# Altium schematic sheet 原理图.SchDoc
size A3
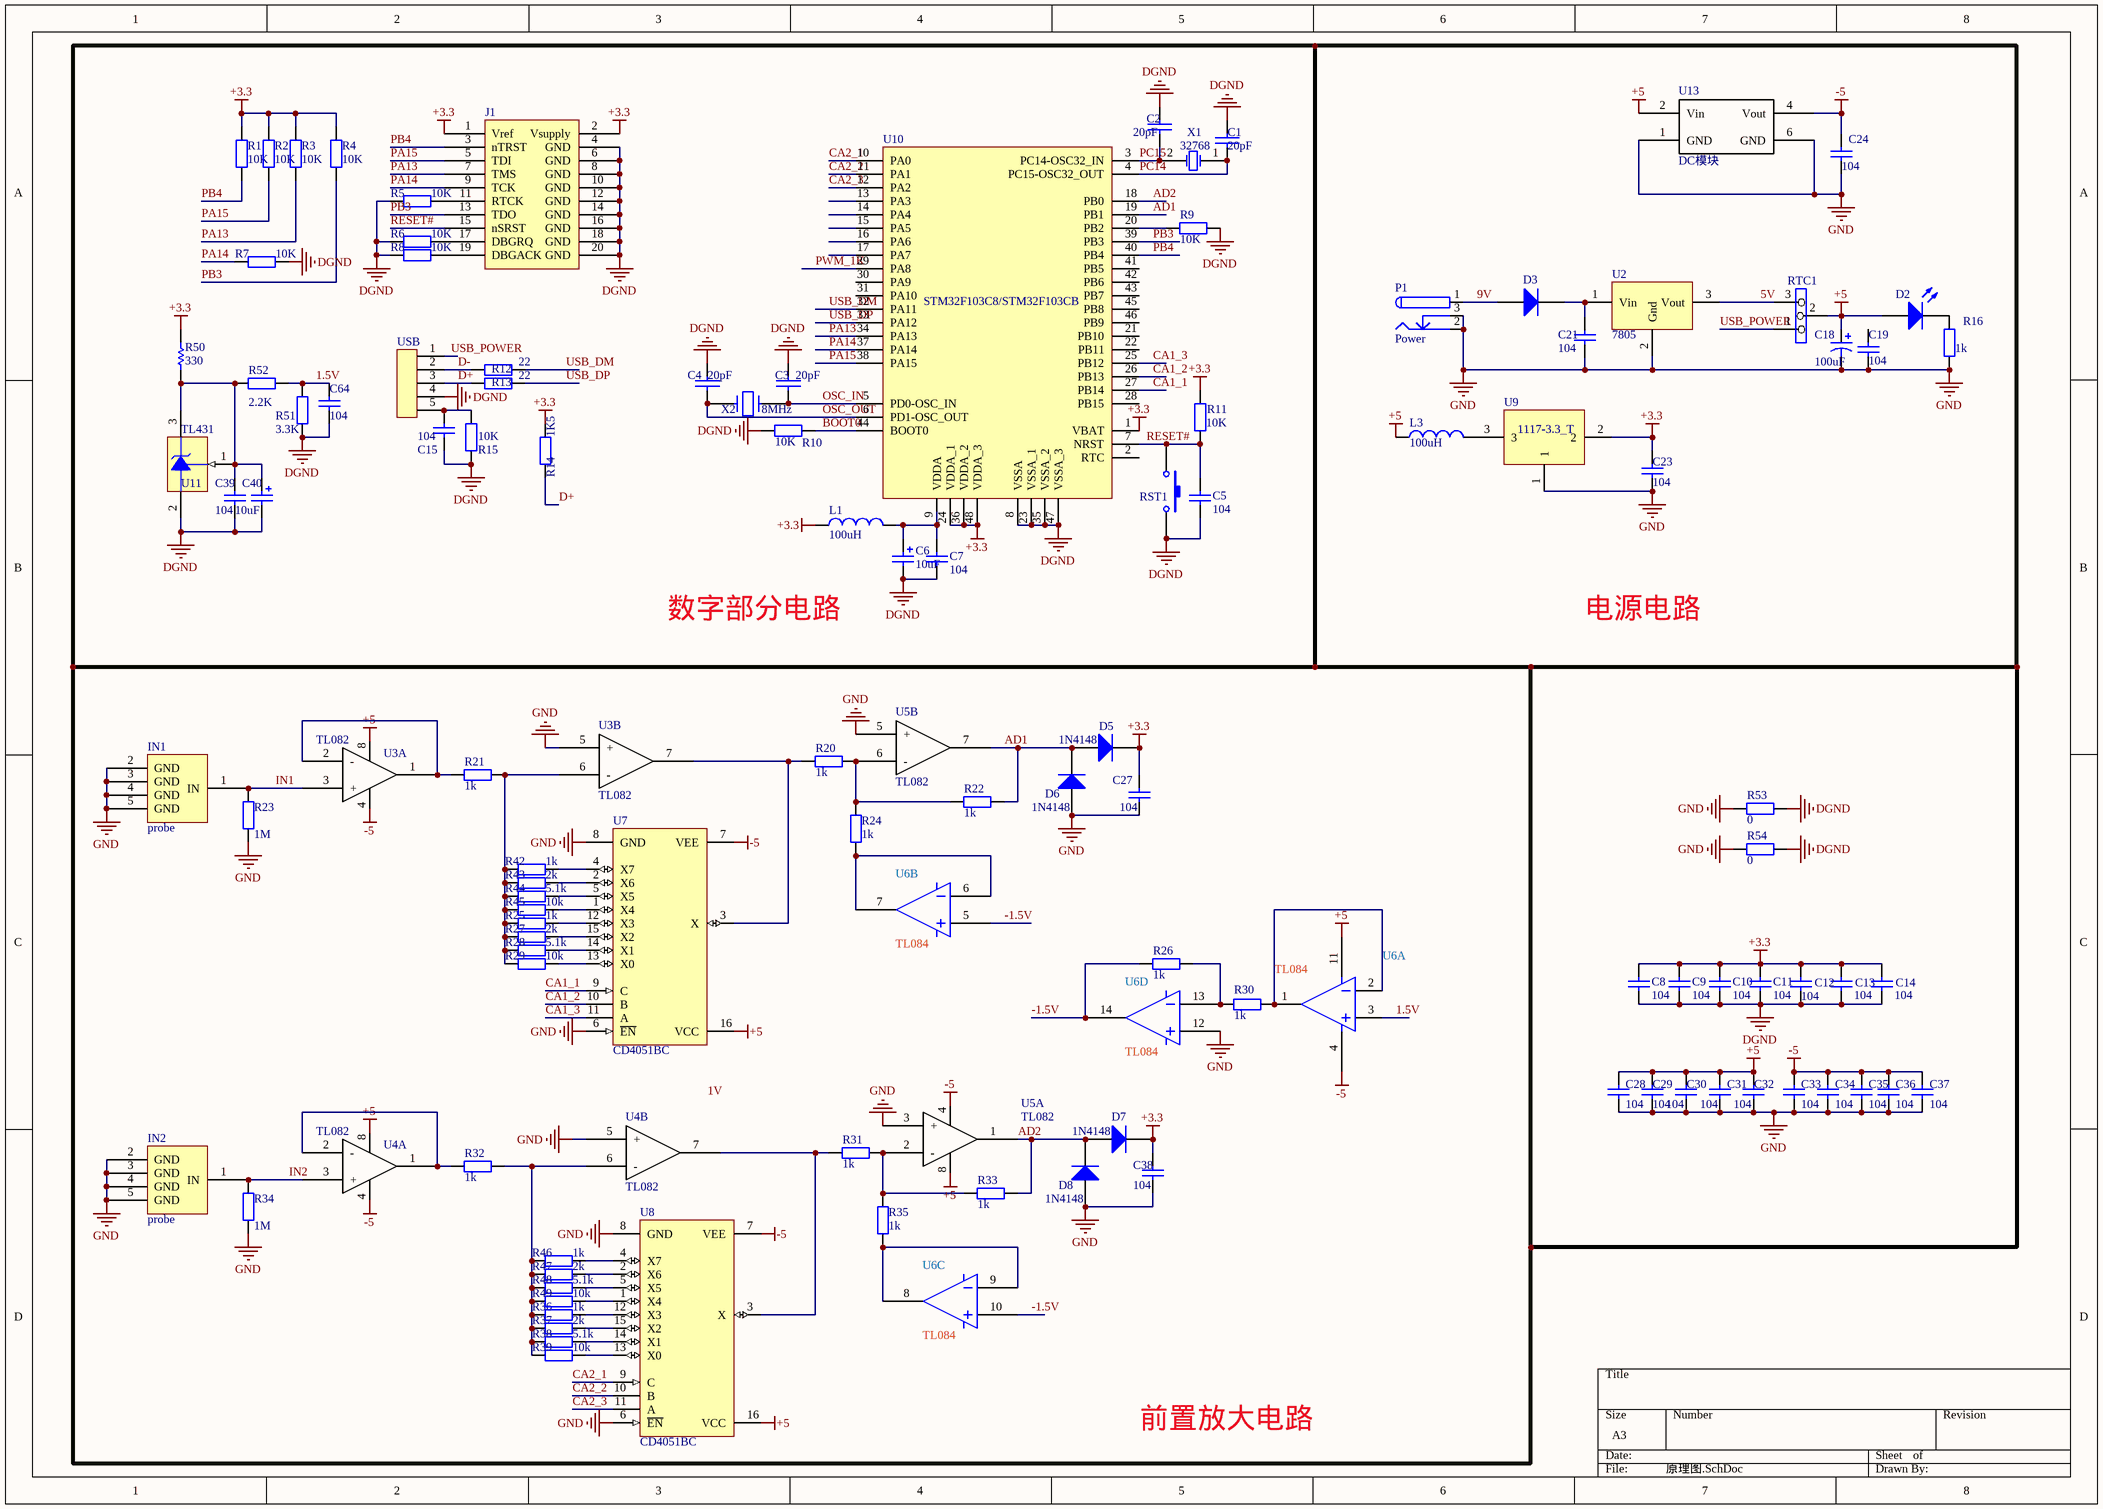
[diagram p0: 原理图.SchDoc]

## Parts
C1  20pF  [C0805]
C2  20pF  [C0805]
C3  20pF  [C0805]
C4  20pF  [C0805]
C5  104  [C0805]
C6  10uF  [C1206]
C7  104  [C0805]
C8  104  [C0805]
C9  104  [C0805]
C10  104  [C0805]
C11  value 104  [C0805]
C12  value 104  [C0805]
C13  104  [C0805]
C14  104  [C0805]
C15  104  [C0805]
C18  value 100uF  [C-100mil]  (hidden comment: 100u)
C19  104  [C0805]
C21  104  [C0805]
C23  104  [C0805]
C24  value 104  [0805]
C27  value 104  [C0805]
C28  104  [C0805]
C29  value 104  [C0805]
C30  value 104  [C0805]
C31  104  [C0805]
C32  value 104  [C0805]
C33  value 104  [C0805]
C34  104  [C0805]
C35  value 104  [C0805]
C36  104  [C0805]
C37  104  [C0805]
C38  value 104  [C0805]
C39  104  [C0805]
C40  10uF  [C1206]
C64  104  [C0805]
D2  LED  [c0805]  (value not drawn)
D3  1N4007  [DO-41]  (value not drawn)
D5  1N4148  [0805D]
D6  1N4148  [0805D]
D7  1N4148  [0805D]
D8  1N4148  [0805D]
IN1  probe  [̽ͷ]
IN2  probe  [̽ͷ]
J1  JTAG connector  [JTAG_20_T]  (value not drawn)
L1  value 100uH  [C0805]
L3  value 100uH  [c0805]
P1  Power  [Power_In]
R1  value 10K  [c0805]  (hidden comment: Res2)
R2  value 10K  [C0805]  (hidden comment: Res2)
R3  value 10K  [C0805]  (hidden comment: Res2)
R4  value 10K  [C0805]  (hidden comment: Res2)
R5  value 10K  [C0805]  (hidden comment: Res2)
R6  value 10K  [C0805]  (hidden comment: Res2)
R7  value 10K  [C0805]  (hidden comment: Res2)
R8  value 10K  [C0805]  (hidden comment: Res2)
R9  value 10K  [C0805]  (hidden comment: Res2)
R10  value 10K  [C0805]  (hidden comment: Res2)
R11  value 10K  [C0805]  (hidden comment: Res2)
R12  value 22  [C0805]
R13  22  [C0805]
R14  1K5  [C0805]
R15  10K  [C0805]
R16  1k  [C0805]
R20  1k  [C0805]
R21  1k  [C0805]
R22  1k  [C0805]
R23  value 1M  [C0805]  (hidden comment: Res2)
R24  1k  [C0805]
R25  1k  [C0805]
R26  1k  [C0805]
R27  value 2k  [C0805]  (hidden comment: 1k)
R28  value 5.1k  [C0805]  (hidden comment: 1k)
R29  value 10k  [C0805]  (hidden comment: 1k)
R30  1k  [C0805]
R31  1k  [C0805]
R32  1k  [C0805]
R33  1k  [C0805]
R34  value 1M  [C0805]  (hidden comment: Res2)
R35  1k  [C0805]
R36  1k  [C0805]
R37  value 2k  [C0805]  (hidden comment: 1k)
R38  value 5.1k  [C0805]  (hidden comment: 1k)
R39  value 10k  [C0805]  (hidden comment: 1k)
R42  1k  [C0805]
R43  value 2k  [C0805]  (hidden comment: 1k)
R44  value 5.1k  [C0805]  (hidden comment: 1k)
R45  value 10k  [C0805]  (hidden comment: 1k)
R46  1k  [C0805]
R47  value 2k  [C0805]  (hidden comment: 1k)
R48  value 5.1k  [C0805]  (hidden comment: 1k)
R49  value 10k  [C0805]  (hidden comment: 1k)
R50  330  [C0805]
R51  value 3.3K  [C0805]
R52  2.2K  [C0805]
R53  value 0  [C0805]  (hidden comment: 1k)
R54  value 0  [C0805]  (hidden comment: 1k)
RST1  SW-PB  [按键]  (value not drawn)
RTC1  (no value)  [PZ3]
U2  7805  [7805]
U3  TL082  [NE5532]  (parts A,B of 2)
U4  TL082  [NE5532]  (parts A,B of 2)
U5  TL082  [NE5532]  (parts A,B of 2)
U6  TL084  [SOIC14_1.27mm]  (parts A,B,C,D of 4)
U7  CD4051BC  [CD4051]
U8  CD4051BC  [CD4051]
U9  (no value)  [SOT223]
U10  STM32F103C8/STM32F103CB  [LQFP48]
U11  TL431  [sot-23]
U13  DC模块  [DC模块]
USB  (no value)  [USB-B]
X1  32768  [XTAL-32768]
X2  8MHz  [XTAL-200mil]

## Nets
+3.3: C8.2 C9.2 C10.2 C11.1 C12.1 C13.2 C14.2 C23.2 C27.1 C38.1 D5.2(K) D7.2(K) J1.1(Vref) J1.2(Vsupply) L1.1 R1.1 R2.1 R3.1 R4.1 R11.1 R14.2 R50.1 U9.2 U10.1(VBAT) U10.24(VDDA_1) U10.36(VDDA_2) U10.48(VDDA_3)
+5: C18.1 C28.1 C29.2 C30.2 C31.1 C32.1 D2.1(A) L3.1 RTC1.2 U3.8 U4.8 U5.8 U6.11 U7.16(VCC) U8.16(VCC) U13.2(Vin)
-5: C24.2 C33.1 C34.1 C35.2 C36.1 C37.1 U3.4 U4.4 U5.4 U6.4 U7.7(VEE) U8.7(VEE) U13.4(Vout)
DGND: C1.2 C2.2 C3.1 C4.1 C5.2 C6.2 C7.2 C8.1 C9.1 C10.1 C11.2 C12.2 C13.1 C14.1 C15.1 C39.1 C40.2 C64.1 J1.4(GND) J1.6(GND) J1.8(GND) J1.10(GND) J1.12(GND) J1.14(GND) J1.16(GND) J1.18(GND) J1.20(GND) R5.2 R6.2 R7.1 R8.1 R9.2 R10.1 R15.1 R51.2 R53.1 R54.1 RST1.1 U10.8(VSSA) U10.23(VSSA_1) U10.35(VSSA_2) U10.47(VSSA_3) U11.2(A) USB.4
GND: C18.2 C19.1 C21.1 C23.1 C24.1 C27.2 C28.2 C29.1 C30.1 C31.2 C32.2 C33.2 C34.2 C35.1 C36.2 C37.2 C38.2 D6.1(A) D8.1(A) IN1.2(GND) IN1.3(GND) IN1.4(GND) IN1.5(GND) IN2.2(GND) IN2.3(GND) IN2.4(GND) IN2.5(GND) P1.2 P1.3 R16.2 R23.1 R34.1 R53.2 R54.2 U2.2(Gnd) U3.5(+) U4.5(+) U5.3(+) U5.5(+) U6.12 U7.6(~{EN}) U7.8(GND) U8.6(~{EN}) U8.8(GND) U9.1 U13.1(GND) U13.6(GND)
1.5V: C64.2 R51.1 R52.1 U6.3
5V: RTC1.3 U2.3(Vout)
9V: D3.1(A) P1.1
-1.5V: R26.2 U6.5 U6.10 U6.14
AD1: D5.1(A) D6.2(K) R22.1 U5.7 U10.19(PB1)
AD2: D7.1(A) D8.2(K) R33.1 U5.1 U10.18(PB0)
BOOT0: R10.2 U10.44(BOOT0)
CA1_1: U7.9(C) U10.27(PB14)
CA1_2: U7.10(B) U10.26(PB13)
CA1_3: U7.11(A) U10.25(PB12)
CA2_1: U8.9(C) U10.10(PA0)
CA2_2: U8.10(B) U10.11(PA1)
CA2_3: U8.11(A) U10.12(PA2)
D+: R13.1 R14.1 USB.3
D-: R12.2 USB.2
IN1: IN1.1(IN) R23.2 U3.3(+)
IN2: IN2.1(IN) R34.2 U4.3(+)
OSC_IN: C3.2 U10.5(PD0-OSC_IN) X2.1
OSC_OUT: C4.2 U10.6(PD1-OSC_OUT) X2.2
PA13: J1.7(TMS) R3.2 U10.34(PA13)
PA14: J1.9(TCK) R7.2 U10.37(PA14)
PA15: J1.5(TDI) R2.2 U10.38(PA15)
PB3: J1.13(TDO) R4.2 U10.39(PB3)
PB4: J1.3(nTRST) R1.2 U10.40(PB4)
PC14: C1.1 U10.4(PC15-OSC32_OUT) X1.1(OSC1)
PC15: C2.1 U10.3(PC14-OSC32_IN) X1.2(OSC2)
PWM_1K: U10.29(PA8)
RESET#: C5.1 J1.15(nSRST) R11.2 RST1.2 U10.7(NRST)
USB_DM: R12.1 U10.32(PA11)
USB_DP: R13.2 U10.33(PA12)
USB_POWER: RTC1.1 USB.1
NetC6_1: C6.1 C7.1 L1.2 U10.9(VDDA)
NetC15_2: C15.2 R15.2 USB.5
NetC21_2: C21.2 D3.2(K) U2.1(Vin)
NetC39_2: C39.2 C40.1 R50.2 R52.2 U11.1(REF) U11.3(K)
NetD2_2: D2.2(K) R16.1
NetJ1_11: J1.11(RTCK) R5.1
NetJ1_17: J1.17(DBGRQ) R6.1
NetJ1_19: J1.19(DBGACK) R8.2
NetL3_2: L3.2 U9.3
NetR9_1: R9.1 U10.20(PB2)
NetR20_1: R20.1 U3.7 U7.3(X)
NetR20_2: R20.2 R22.2 R24.2 U5.6(-)
NetR21_1: R21.1 U3.1 U3.2(-)
NetR21_2: R21.2 R25.1 R27.1 R28.1 R29.1 R42.1 R43.1 R44.1 R45.1 U3.6(-)
NetR24_1: R24.1 U6.6 U6.7
NetR25_2: R25.2 U7.12(X3)
NetR26_1: R26.1 R30.2 U6.13
NetR27_2: R27.2 U7.15(X2)
NetR28_2: R28.2 U7.14(X1)
NetR29_2: R29.2 U7.13(X0)
NetR30_1: R30.1 U6.1 U6.2
NetR31_1: R31.1 U4.7 U8.3(X)
NetR31_2: R31.2 R33.2 R35.2 U5.2(-)
NetR32_1: R32.1 U4.1 U4.2(-)
NetR32_2: R32.2 R36.1 R37.1 R38.1 R39.1 R46.1 R47.1 R48.1 R49.1 U4.6(-)
NetR35_1: R35.1 U6.8 U6.9
NetR36_2: R36.2 U8.12(X3)
NetR37_2: R37.2 U8.15(X2)
NetR38_2: R38.2 U8.14(X1)
NetR39_2: R39.2 U8.13(X0)
NetR42_2: R42.2 U7.4(X7)
NetR43_2: R43.2 U7.2(X6)
NetR44_2: R44.2 U7.5(X5)
NetR45_2: R45.2 U7.1(X4)
NetR46_2: R46.2 U8.4(X7)
NetR47_2: R47.2 U8.2(X6)
NetR48_2: R48.2 U8.5(X5)
NetR49_2: R49.2 U8.1(X4)

Not connected (* = marked no-connect by the designer): C19 2; U10 2(RTC) 13(PA3) 14(PA4) 15(PA5) 16(PA6) 17(PA7) 21(PB10) 22(PB11) 28(PB15) 30(PA9) 31(PA10) 41(PB5) 42(PB6) 43(PB7) 45(PB8) 46(PB9)

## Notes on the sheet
- 数字部分电路
- 电源电路
- 前置放大电路
- Labels drawn without touching a wire or pin: 1V

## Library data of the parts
C1-C4 = CAP: Capacitor
C5 = CAP: Capacitor; Value: 100pF
C6 C18 C40 = Cap Pol1: Polarized Capacitor (Radial)
C7 = Cap: Capacitor; Value: 103
C8-C14 C19 C21 C23 C24 C27-C39 = Cap: Capacitor
C15 C64 = Cap: Capacitor; Value: 10nF
D2 = LED0: Typical INFRARED GaAs LED
D3 = Diode 1N4007: 1 Amp General Purpose Rectifier
D5-D8 = Diode: Default Diode
J1 U11 = Component_1
L1 = Inductor
L3 = Inductor: Code_IEC: 1005
P1 = Power: 电源接头
R1-R16 R20-R39 R42-R49 R51-R54 = Res2: Resistor
R50 = Res1: Resistor; Value: 1K
RST1 = SW-PB: Switch
RTC1 = Jumper3
U2 = 7805: 5V电源芯片
U3-U5 = NE5532: 常用运放
U6 = LM124
U7 U8 = CD4051BC: 8-Channel Analog Multiplexer/Demultiplexer
U9 = 1117-3.3
U10 = STM32f103_48pIN
USB = Header5: 排针5
X1 = XTAL: Crystal Oscillator
X2 = CRYSTAL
